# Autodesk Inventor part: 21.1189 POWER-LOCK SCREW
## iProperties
Created: 2006-02
Part Number: 21.1189 POWER-LOCK SCREW
Material: Steel, Mild
Description: Cylinder Head Cap Screw
Document SubType Name: Modeling
Standard: DIN 7984
Designer: Andy Moles
Standards Organization: DIN
Language: en-US
Size Designation: M8 x 25
Categories: <MemberInstance><Categories><Category DisplayName="Fasteners" InternalName="e4da775c-781d-43d5-af7c-5136215cf5a6" Mnemonic="FSTN"><Category DisplayName="Bolts"
Density: 7.86 g/cm^3
Mass: 13.063 g
Surface Area: 10.8236 cm^2
Volume: 1.66196 cm^3
Author: Andy Moles
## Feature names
1. Body [Revolution]
2. Slot [Extrusion]
3. Chamfer1
